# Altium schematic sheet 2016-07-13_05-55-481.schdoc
size 374 x 119 mm; SheetNumber: 1; SheetTotal: 1
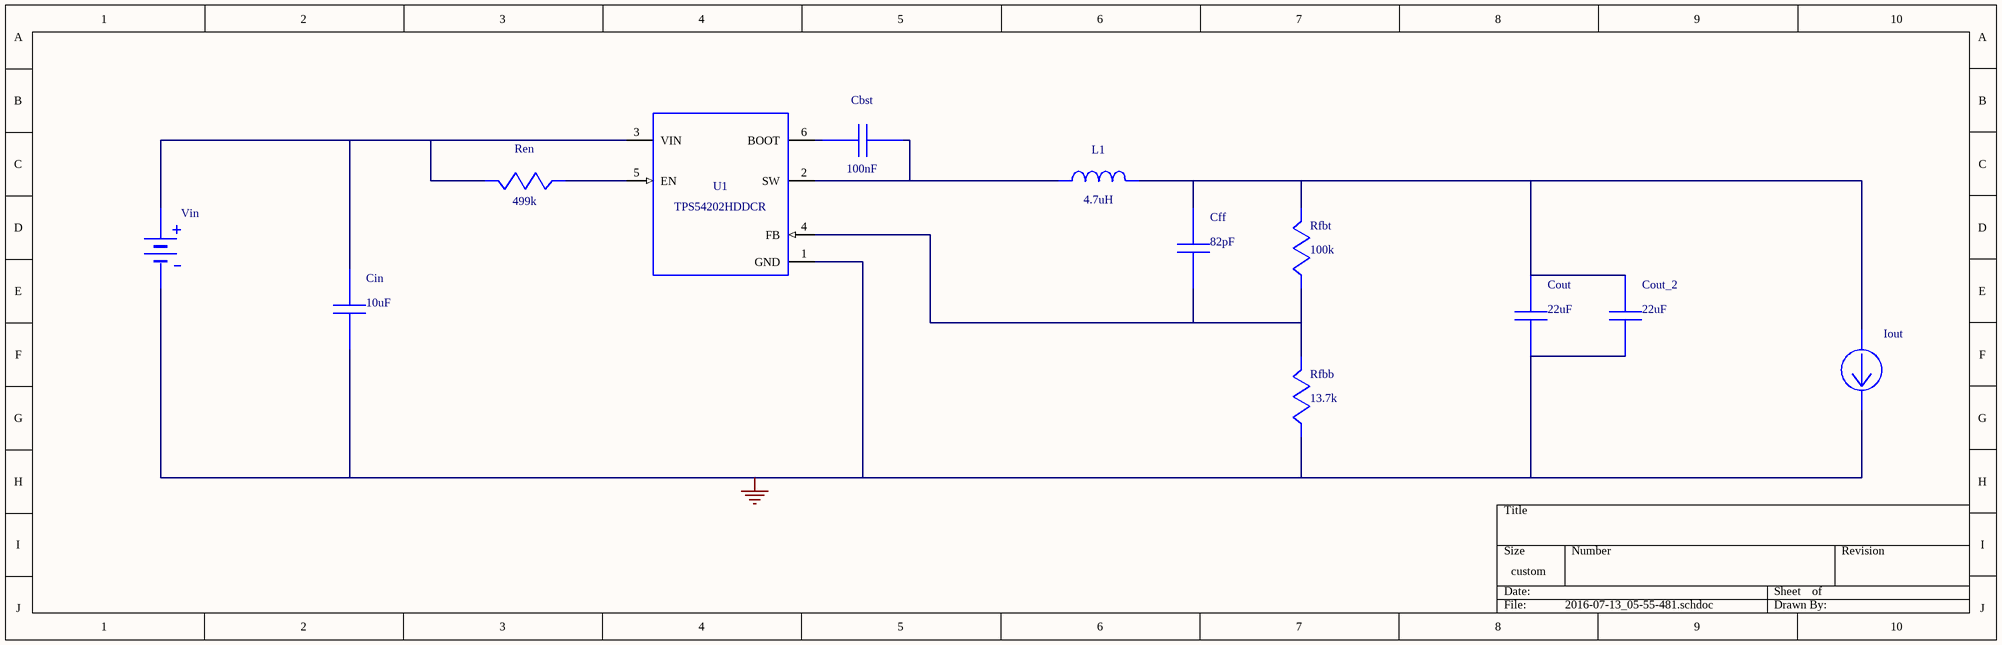
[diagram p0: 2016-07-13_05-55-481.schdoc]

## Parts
Cbst  value 100nF  (hidden comment: 08053C104KAT2A)
Cff  value 82pF  (hidden comment: C0603C0G1E820K030BA)
Cin  value 10uF  (hidden comment: GRM31CR61E106KA12L)
Cout  value 22uF  (hidden comment: C4532X5R1E226M)
Cout_2  value 22uF  (hidden comment: C4532X5R1E226M)
Iout  WB_CURRENT_LOAD  (value not drawn)
L1  value 4.7uH  (hidden comment: XFL4020-472MEB)
Ren  value 499k  (hidden comment: CRCW0402499KFKED)
Rfbb  value 13.7k  (hidden comment: CRCW040213K7FKED)
Rfbt  value 100k  (hidden comment: CRCW0402100KFKED)
U1  TPS54202HDDCR
Vin  WB_BATTERY  (value not drawn)

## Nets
0: Cin.2 Cout.2 Cout_2.2 Iout.2(-) Rfbb.2 U1.1(GND) Vin.2(-)
NetCbst_1: Cbst.1 U1.6(BOOT)
NetCbst_2: Cbst.2 L1.1 U1.2(SW)
NetCff_1: Cff.1 Cout.1 Cout_2.1 Iout.1(+) L1.2 Rfbt.1
NetCff_2: Cff.2 Rfbb.1 Rfbt.2 U1.4(FB)
NetCin_1: Cin.1 Ren.1 U1.3(VIN) Vin.1(+)
NetRen_2: Ren.2 U1.5(EN)

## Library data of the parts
Cbst = 08053C104KAT2A: Manufacturer Name: AVX
Cff = C0603C0G1E820K030BA: C0603C0G1E820K03; Manufacturer Name: TDK
Cin = GRM31CR61E106KA12L: GRM31CR61E106KA1; Manufacturer Name: MuRata
Cout Cout_2 = C4532X5R1E226M: Manufacturer Name: TDK
L1 = XFL4020-472MEB: Manufacturer Name: Coilcraft
Ren = CRCW0402499KFKED: Manufacturer Name: Vishay-Dale
Rfbb = CRCW040213K7FKED: Manufacturer Name: Vishay-Dale
Rfbt = CRCW0402100KFKED: Manufacturer Name: Vishay-Dale
U1 = TPS54202HDDCR: Manufacturer Name: Texas Instruments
